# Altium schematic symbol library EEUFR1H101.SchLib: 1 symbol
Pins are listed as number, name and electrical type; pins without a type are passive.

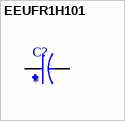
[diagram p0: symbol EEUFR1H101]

## EEUFR1H101
designator C?
100F 50V Aluminum Electrolytic Capacitors Radial, Can 6000 Hrs @ 105C; MP: EEU-FR1H101; MF: Panasonic
footprint CAPPRD350W60D800H1150
pins: N, P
